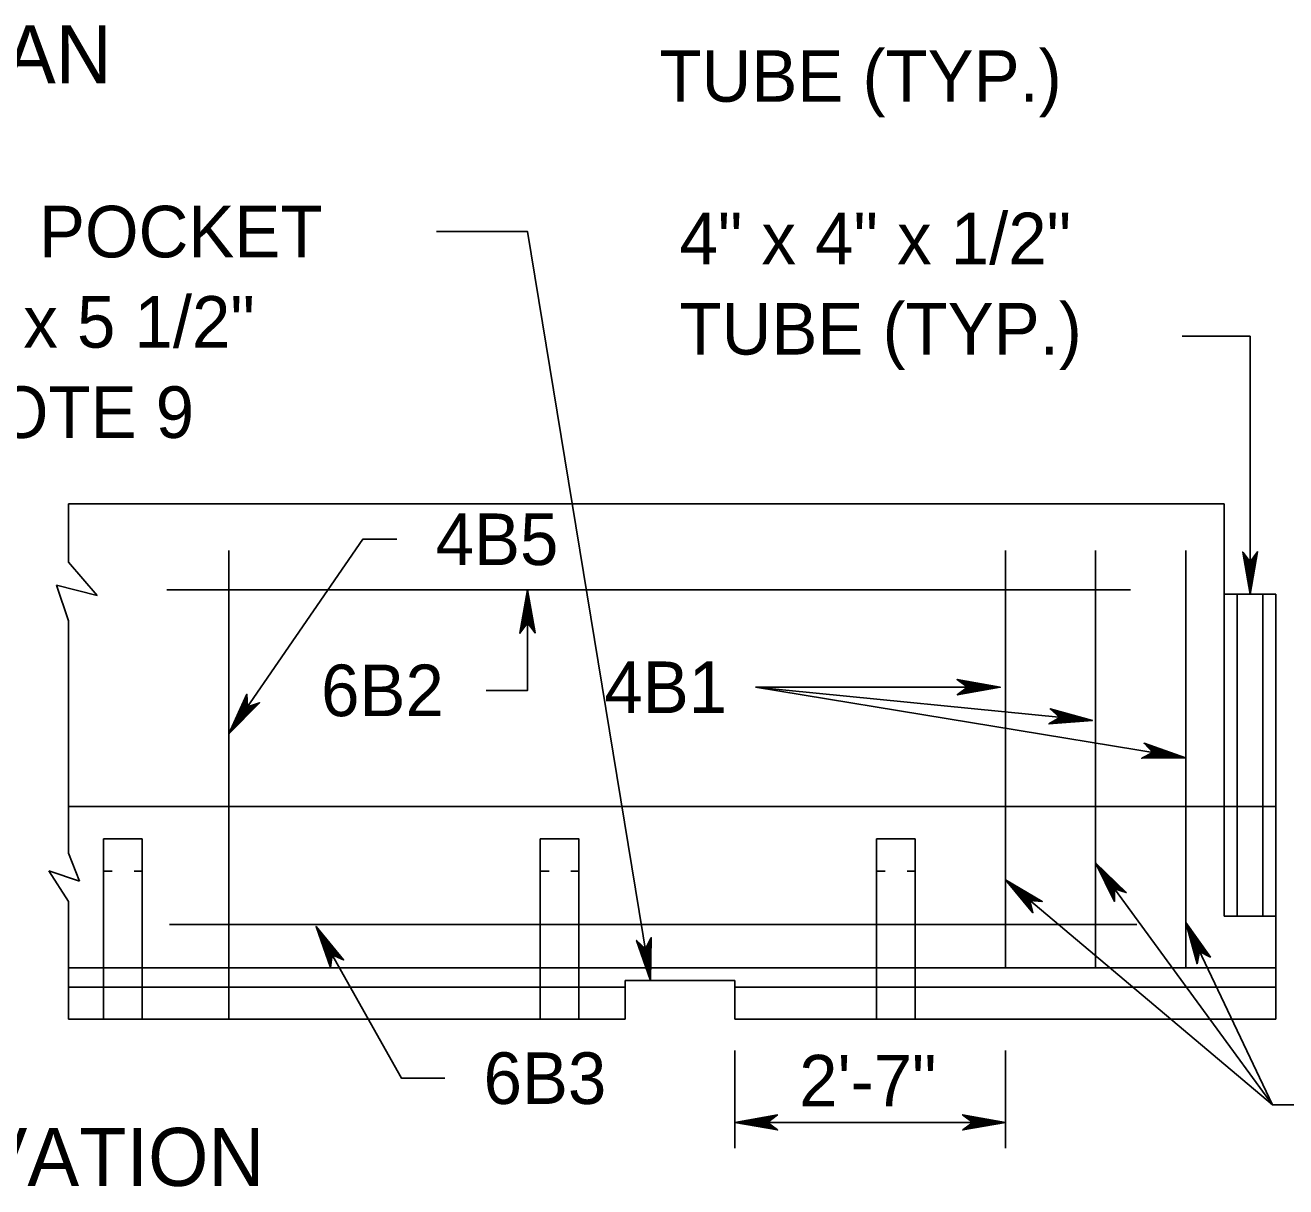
# Model space of a CAD drawing. Extents: x 499866 to 500993, y 499985 to 500645.
# Drawn here: x 500361.2 to 500459, y 500116.7 to 500206.8 of the extents above; entities that cross this region are included whole.
import ezdxf

# ---------------------------------------------------------------- set-up
doc = ezdxf.new("R2010")
doc.units = 0
doc.layers.add('24', color=7, linetype='Continuous')
doc.layers.add('5', color=7, linetype='Continuous')

msp = doc.modelspace()

# ---------------------------------------------------------------- linework, layer by layer
at = {"layer": '24'}
for points in [[(500456.223, 500162.67), (500456.802, 500165.944), (500456.223, 500165.162), (500455.653, 500165.927), (500456.223, 500162.67), (500456.217, 500162.887), (500456.759, 500165.852), (500456.216, 500165.101), (500455.698, 500165.795), (500456.207, 500163.005), (500456.223, 500163.114), (500456.675, 500165.654), (500456.216, 500165.084), (500455.772, 500165.67), (500456.223, 500163.164), (500456.207, 500163.273), (500456.608, 500165.493), (500456.223, 500165.061), (500455.824, 500165.502), (500456.206, 500163.589), (500456.207, 500163.773), (500456.525, 500165.328), (500456.232, 500165.026), (500455.907, 500165.351), (500456.223, 500163.806), (500456.233, 500163.981), (500456.433, 500165.15), (500456.206, 500164.925), (500455.982, 500165.169), (500456.223, 500164.142), (500456.24, 500164.307), (500456.374, 500165.009), (500456.216, 500164.893), (500456.041, 500165.084), (500456.223, 500164.392), (500456.332, 500164.85), (500456.207, 500164.784), (500456.081, 500164.985), (500456.206, 500164.508), (500456.282, 500164.808), (500456.183, 500164.682), (500456.124, 500164.826), (500456.216, 500164.683), (500456.232, 500164.758)], [(500400.181, 500162.984), (500400.181, 500155.199), (500396.976, 500155.199)], [(500400.181, 500162.984), (500399.589, 500159.634), (500400.181, 500160.434), (500400.764, 500159.651), (500400.181, 500162.984), (500400.187, 500162.761), (500399.633, 500159.727), (500400.189, 500160.496), (500400.719, 500159.786), (500400.198, 500162.641), (500400.181, 500162.53), (500399.72, 500159.931), (500400.188, 500160.514), (500400.643, 500159.914), (500400.181, 500162.478), (500400.198, 500162.367), (500399.788, 500160.095), (500400.181, 500160.537), (500400.59, 500160.086), (500400.199, 500162.044), (500400.198, 500161.855), (500399.872, 500160.264), (500400.172, 500160.573), (500400.505, 500160.24), (500400.181, 500161.821), (500400.171, 500161.642), (500399.966, 500160.446), (500400.199, 500160.676), (500400.428, 500160.427), (500400.181, 500161.478), (500400.164, 500161.309), (500400.027, 500160.591), (500400.189, 500160.709), (500400.367, 500160.513), (500400.181, 500161.221), (500400.07, 500160.753), (500400.198, 500160.821), (500400.326, 500160.615), (500400.199, 500161.104), (500400.121, 500160.796), (500400.222, 500160.925), (500400.283, 500160.777), (500400.189, 500160.924), (500400.172, 500160.847)], [(500436.846, 500155.439), (500433.496, 500156.031), (500434.297, 500155.439), (500433.513, 500154.856), (500436.846, 500155.439), (500436.624, 500155.433), (500433.59, 500155.987), (500434.359, 500155.432), (500433.649, 500154.902), (500436.504, 500155.423), (500436.392, 500155.439), (500433.793, 500155.901), (500434.376, 500155.432), (500433.777, 500154.977), (500436.341, 500155.439), (500436.23, 500155.423), (500433.958, 500155.833), (500434.4, 500155.439), (500433.949, 500155.031), (500435.906, 500155.422), (500435.717, 500155.423), (500434.127, 500155.748), (500434.436, 500155.448), (500434.103, 500155.115), (500435.683, 500155.439), (500435.505, 500155.449), (500434.309, 500155.654), (500434.539, 500155.422), (500434.289, 500155.193), (500435.34, 500155.439), (500435.172, 500155.456), (500434.453, 500155.593), (500434.572, 500155.432), (500434.376, 500155.253), (500435.084, 500155.439), (500434.615, 500155.551), (500434.683, 500155.423), (500434.478, 500155.294), (500434.966, 500155.422), (500434.659, 500155.499), (500434.788, 500155.398), (500434.64, 500155.338), (500434.787, 500155.432), (500434.71, 500155.448)], [(500377.004, 500151.821), (500379.393, 500154.243), (500378.451, 500153.92), (500378.415, 500154.896), (500377.004, 500151.821), (500377.126, 500152.008), (500379.303, 500154.191), (500378.409, 500153.873), (500378.376, 500154.759), (500377.185, 500152.112), (500377.262, 500152.195), (500379.117, 500154.073), (500378.4, 500153.859), (500378.366, 500154.61), (500377.291, 500152.237), (500377.341, 500152.338), (500378.967, 500153.976), (500378.392, 500153.835), (500378.312, 500154.438), (500377.524, 500152.605), (500377.631, 500152.76), (500378.802, 500153.885), (500378.38, 500153.8), (500378.295, 500154.263), (500377.664, 500152.778), (500377.774, 500152.92), (500378.621, 500153.788), (500378.3, 500153.731), (500378.252, 500154.066), (500377.859, 500153.061), (500377.969, 500153.19), (500378.489, 500153.704), (500378.289, 500153.698), (500378.253, 500153.96), (500378.004, 500153.272), (500378.362, 500153.594), (500378.218, 500153.611), (500378.229, 500153.853), (500378.057, 500153.379), (500378.295, 500153.588), (500378.138, 500153.539), (500378.173, 500153.695), (500378.167, 500153.521), (500378.224, 500153.574)], [(500444.002, 500152.857), (500440.726, 500153.776), (500441.465, 500153.108), (500440.628, 500152.604), (500444.002, 500152.857), (500443.78, 500152.873), (500440.815, 500153.722), (500441.526, 500153.094), (500440.767, 500152.637), (500443.659, 500152.874), (500443.55, 500152.902), (500441.009, 500153.617), (500441.543, 500153.093), (500440.902, 500152.699), (500443.499, 500152.907), (500443.387, 500152.901), (500441.167, 500153.532), (500441.568, 500153.098), (500441.078, 500152.735), (500443.065, 500152.932), (500442.877, 500152.951), (500441.326, 500153.432), (500441.604, 500153.103), (500441.24, 500152.804), (500442.845, 500152.971), (500442.668, 500152.999), (500441.498, 500153.321), (500441.704, 500153.067), (500441.433, 500152.863), (500442.503, 500153.005), (500442.337, 500153.038), (500441.636, 500153.245), (500441.738, 500153.073), (500441.526, 500152.915), (500442.248, 500153.031), (500441.793, 500153.187), (500441.848, 500153.053), (500441.631, 500152.946), (500442.13, 500153.025), (500441.831, 500153.132), (500441.949, 500153.018), (500441.796, 500152.973), (500441.952, 500153.052), (500441.877, 500153.076)], [(500451.208, 500149.974), (500447.998, 500151.1), (500448.692, 500150.386), (500447.825, 500149.938), (500451.208, 500149.974), (500450.988, 500150.004), (500448.084, 500151.042), (500448.753, 500150.369), (500447.966, 500149.961), (500450.868, 500150.013), (500450.76, 500150.048), (500448.27, 500150.924), (500448.77, 500150.366), (500448.105, 500150.015), (500450.71, 500150.056), (500450.597, 500150.057), (500448.422, 500150.829), (500448.794, 500150.37), (500448.283, 500150.039), (500450.278, 500150.109), (500450.092, 500150.14), (500448.574, 500150.719), (500448.831, 500150.373), (500448.449, 500150.098), (500450.061, 500150.162), (500449.886, 500150.201), (500448.739, 500150.597), (500448.928, 500150.33), (500448.645, 500150.145), (500449.722, 500150.218), (500449.559, 500150.262), (500448.872, 500150.513), (500448.963, 500150.335), (500448.74, 500150.19), (500449.47, 500150.259), (500449.025, 500150.445), (500449.072, 500150.307), (500448.848, 500150.214), (500449.35, 500150.261), (500449.059, 500150.387), (500449.17, 500150.266), (500449.015, 500150.231), (500449.175, 500150.3), (500449.102, 500150.329)], [(500444.239, 500141.817), (500445.706, 500138.834), (500445.711, 500139.806), (500446.622, 500139.525), (500444.239, 500141.817), (500444.372, 500141.645), (500445.687, 500138.933), (500445.681, 500139.86), (500446.508, 500139.606), (500444.45, 500141.556), (500444.501, 500141.459), (500445.637, 500139.143), (500445.67, 500139.873), (500446.375, 500139.663), (500444.531, 500141.419), (500444.608, 500141.341), (500445.596, 500139.312), (500445.651, 500139.888), (500446.234, 500139.768), (500444.795, 500141.086), (500444.904, 500140.936), (500445.565, 500139.494), (500445.623, 500139.911), (500446.078, 500139.84), (500444.91, 500140.9), (500445.005, 500140.753), (500445.534, 500139.692), (500445.584, 500140.007), (500445.909, 500139.943), (500445.108, 500140.63), (500445.193, 500140.487), (500445.499, 500139.841), (500445.558, 500140.028), (500445.812, 500139.976), (500445.256, 500140.427), (500445.439, 500139.994), (500445.501, 500140.121), (500445.72, 500140.033), (500445.338, 500140.344), (500445.454, 500140.058), (500445.46, 500140.218), (500445.593, 500140.136), (500445.433, 500140.198), (500445.465, 500140.127)], [(500437.244, 500140.501), (500439.376, 500137.95), (500439.151, 500138.896), (500440.103, 500138.839), (500437.244, 500140.501), (500437.414, 500140.365), (500439.334, 500138.041), (500439.108, 500138.941), (500439.973, 500138.89), (500437.511, 500140.297), (500437.584, 500140.215), (500439.236, 500138.234), (500439.095, 500138.951), (500439.83, 500138.914), (500437.622, 500140.182), (500437.716, 500140.125), (500439.156, 500138.389), (500439.073, 500138.961), (500439.668, 500138.983), (500437.958, 500139.922), (500438.098, 500139.802), (500439.083, 500138.558), (500439.04, 500138.976), (500439.499, 500139.016), (500438.114, 500139.769), (500438.24, 500139.649), (500439.006, 500138.743), (500438.98, 500139.061), (500439.311, 500139.076), (500438.37, 500139.553), (500438.486, 500139.434), (500438.936, 500138.879), (500438.949, 500139.074), (500439.208, 500139.085), (500438.561, 500139.391), (500438.842, 500139.013), (500438.872, 500139.152), (500439.106, 500139.119), (500438.661, 500139.33), (500438.842, 500139.079), (500438.809, 500139.236), (500438.958, 500139.188), (500438.789, 500139.21), (500438.836, 500139.149)], [(500383.782, 500136.901), (500390.403, 500125.131), (500393.772, 500125.131)], [(500383.782, 500136.901), (500384.9, 500133.716), (500385.023, 500134.697), (500385.907, 500134.303), (500383.782, 500136.901), (500383.896, 500136.712), (500384.892, 500133.819), (500384.998, 500134.754), (500385.802, 500134.398), (500383.963, 500136.613), (500384.003, 500136.509), (500384.868, 500134.037), (500384.99, 500134.769), (500385.675, 500134.472), (500384.028, 500136.464), (500384.096, 500136.377), (500384.847, 500134.212), (500384.972, 500134.786), (500385.545, 500134.594), (500384.254, 500136.096), (500384.346, 500135.933), (500384.838, 500134.399), (500384.947, 500134.812), (500385.397, 500134.686), (500384.348, 500135.896), (500384.426, 500135.736), (500384.831, 500134.602), (500384.919, 500134.914), (500385.239, 500134.81), (500384.515, 500135.599), (500384.582, 500135.445), (500384.813, 500134.757), (500384.895, 500134.938), (500385.145, 500134.856), (500384.639, 500135.377), (500384.771, 500134.918), (500384.849, 500135.039), (500385.06, 500134.924), (500384.712, 500135.284), (500384.794, 500134.98), (500384.819, 500135.141), (500384.943, 500135.043), (500384.79, 500135.124), (500384.813, 500135.049)], [(500451.234, 500137.21), (500452.118, 500134.006), (500452.305, 500134.961), (500453.149, 500134.515), (500451.234, 500137.21), (500451.332, 500137.017), (500452.118, 500134.107), (500452.285, 500135.019), (500453.051, 500134.615), (500451.392, 500136.915), (500451.425, 500136.81), (500452.109, 500134.323), (500452.277, 500135.034), (500452.931, 500134.696), (500451.445, 500136.764), (500451.507, 500136.673), (500452.1, 500134.497), (500452.261, 500135.052), (500452.811, 500134.826), (500451.643, 500136.388), (500451.722, 500136.221), (500452.104, 500134.681), (500452.238, 500135.08), (500452.672, 500134.926), (500451.722, 500136.184), (500451.788, 500136.022), (500452.11, 500134.881), (500452.218, 500135.182), (500452.525, 500135.058), (500451.866, 500135.882), (500451.922, 500135.726), (500452.103, 500135.034), (500452.196, 500135.206), (500452.436, 500135.109), (500451.974, 500135.656), (500452.073, 500135.196), (500452.157, 500135.309), (500452.357, 500135.182), (500452.039, 500135.558), (500452.1, 500135.255), (500452.135, 500135.411), (500452.25, 500135.306), (500452.105, 500135.396), (500452.122, 500135.322)], [(500409.731, 500132.693), (500409.771, 500136.017), (500409.327, 500135.152), (500408.641, 500135.815), (500409.731, 500132.693), (500409.69, 500132.906), (500409.743, 500135.92), (500409.33, 500135.09), (500408.706, 500135.692), (500409.661, 500133.021), (500409.659, 500133.131), (500409.693, 500135.71), (500409.333, 500135.074), (500408.799, 500135.58), (500409.651, 500133.18), (500409.617, 500133.285), (500409.653, 500135.541), (500409.344, 500135.052), (500408.878, 500135.422), (500409.565, 500133.596), (500409.536, 500133.779), (500409.598, 500135.365), (500409.358, 500135.019), (500408.984, 500135.287), (500409.547, 500133.814), (500409.529, 500133.988), (500409.536, 500135.174), (500409.349, 500134.915), (500409.088, 500135.12), (500409.492, 500134.145), (500409.482, 500134.311), (500409.5, 500135.025), (500409.364, 500134.885), (500409.16, 500135.046), (500409.452, 500134.392), (500409.485, 500134.862), (500409.372, 500134.776), (500409.216, 500134.954), (500409.417, 500134.503), (500409.442, 500134.812), (500409.365, 500134.672), (500409.283, 500134.805), (500409.397, 500134.678), (500409.402, 500134.755)], [(500416.254, 500121.701), (500419.577, 500121.114), (500418.783, 500121.701), (500419.56, 500122.28), (500416.254, 500121.701), (500416.474, 500121.708), (500419.484, 500121.157), (500418.721, 500121.708), (500419.426, 500122.234), (500416.594, 500121.718), (500416.704, 500121.701), (500419.283, 500121.243), (500418.704, 500121.708), (500419.299, 500122.159), (500416.755, 500121.701), (500416.865, 500121.718), (500419.119, 500121.311), (500418.681, 500121.701), (500419.128, 500122.107), (500417.186, 500121.718), (500417.374, 500121.718), (500418.952, 500121.395), (500418.645, 500121.692), (500418.975, 500122.023), (500417.407, 500121.701), (500417.585, 500121.691), (500418.771, 500121.488), (500418.543, 500121.718), (500418.79, 500121.946), (500417.748, 500121.701), (500417.915, 500121.684), (500418.628, 500121.548), (500418.51, 500121.708), (500418.705, 500121.886), (500418.002, 500121.701), (500418.467, 500121.591), (500418.4, 500121.718), (500418.604, 500121.845), (500418.119, 500121.718), (500418.424, 500121.642), (500418.296, 500121.742), (500418.443, 500121.802), (500418.297, 500121.708), (500418.373, 500121.692)], [(500437.244, 500121.701), (500433.921, 500122.289), (500434.714, 500121.701), (500433.937, 500121.123), (500437.244, 500121.701), (500437.023, 500121.695), (500434.013, 500122.245), (500434.777, 500121.694), (500434.072, 500121.169), (500436.905, 500121.685), (500436.794, 500121.701), (500434.215, 500122.159), (500434.794, 500121.695), (500434.199, 500121.243), (500436.743, 500121.702), (500436.633, 500121.685), (500434.379, 500122.092), (500434.817, 500121.702), (500434.37, 500121.296), (500436.311, 500121.684), (500436.124, 500121.685), (500434.546, 500122.008), (500434.853, 500121.711), (500434.523, 500121.38), (500436.091, 500121.701), (500435.913, 500121.712), (500434.726, 500121.915), (500434.955, 500121.684), (500434.708, 500121.457), (500435.75, 500121.701), (500435.582, 500121.718), (500434.87, 500121.854), (500434.988, 500121.694), (500434.793, 500121.517), (500435.496, 500121.702), (500435.031, 500121.812), (500435.098, 500121.685), (500434.894, 500121.558), (500435.379, 500121.684), (500435.074, 500121.761), (500435.202, 500121.66), (500435.055, 500121.6), (500435.201, 500121.694), (500435.124, 500121.711)]]:
    msp.add_lwpolyline(points, dxfattribs=at)
at = {"layer": '5'}
for p, q in [((500454.224, 500169.665), (500364.572, 500169.665)), ((500364.572, 500169.665), (500364.572, 500165.134)), ((500454.224, 500169.665), (500454.224, 500162.67)), ((500377.004, 500166.05), (500377.004, 500129.696)), ((500437.244, 500166.05), (500437.244, 500133.692)), ((500444.239, 500166.05), (500444.239, 500133.692)), ((500451.234, 500166.05), (500451.234, 500133.692)), ((500364.572, 500165.134), (500366.809, 500162.562)), ((500364.572, 500160.583), (500363.643, 500163.353)), ((500363.643, 500163.353), (500366.809, 500162.562)), ((500372.202, 500162.984), (500446.941, 500162.984)), ((500454.224, 500162.67), (500454.224, 500137.689)), ((500458.222, 500162.67), (500454.224, 500162.67)), ((500455.224, 500162.67), (500455.224, 500137.689)), ((500457.222, 500162.67), (500457.222, 500137.689)), ((500458.222, 500162.67), (500458.222, 500129.696)), ((500364.572, 500160.583), (500364.572, 500142.579)), ((500417.853, 500155.439), (500436.846, 500155.439)), ((500417.853, 500155.439), (500444.002, 500152.857)), ((500417.853, 500155.439), (500451.208, 500149.974)), ((500458.222, 500146.183), (500364.572, 500146.183)), ((500367.291, 500143.685), (500367.291, 500129.696)), ((500370.288, 500143.685), (500370.288, 500129.696)), ((500401.165, 500143.685), (500401.165, 500129.696)), ((500404.163, 500143.685), (500404.163, 500129.696)), ((500427.245, 500143.685), (500427.245, 500129.696)), ((500430.243, 500143.685), (500430.243, 500129.696)), ((500364.572, 500142.579), (500365.424, 500140.403)), ((500444.239, 500141.817), (500457.976, 500123.053)), ((500364.572, 500138.82), (500363.05, 500141.194)), ((500363.05, 500141.194), (500365.424, 500140.403)), ((500364.572, 500138.82), (500364.572, 500129.696)), ((500458.222, 500137.689), (500454.224, 500137.689)), ((500372.409, 500137.051), (500447.429, 500137.051)), ((500451.234, 500137.21), (500457.976, 500123.053)), ((500395.397, 500133.692), (500364.572, 500133.692)), ((500371.334, 500133.692), (500366.09, 500133.692)), ((500458.222, 500133.692), (500395.397, 500133.692)), ((500416.254, 500132.693), (500407.76, 500132.693)), ((500407.76, 500132.693), (500407.76, 500129.696)), ((500416.254, 500132.693), (500416.254, 500129.696)), ((500407.76, 500132.194), (500364.572, 500132.194)), ((500458.222, 500132.194), (500416.254, 500132.194)), ((500395.397, 500129.696), (500364.572, 500129.696)), ((500371.334, 500129.696), (500366.09, 500129.696)), ((500407.76, 500129.696), (500395.397, 500129.696)), ((500458.222, 500129.696), (500416.254, 500129.696)), ((500416.254, 500127.281), (500416.254, 500119.703)), ((500437.244, 500127.281), (500437.244, 500119.703)), ((500416.254, 500121.701), (500437.244, 500121.701))]:
    msp.add_line(p, q, dxfattribs=at)
for points in [[(500393.131, 500190.771), (500400.188, 500190.771), (500409.731, 500132.693)], [(500450.949, 500182.655), (500456.223, 500182.655), (500456.223, 500162.67)], [(500390.054, 500166.915), (500387.405, 500166.915), (500377.004, 500151.821)], [(500369.673, 500141.172), (500370.283, 500141.172), (500370.288, 500143.685), (500367.291, 500143.685)], [(500367.291, 500143.685), (500367.291, 500141.172), (500367.972, 500141.172)], [(500403.547, 500141.172), (500404.157, 500141.172), (500404.163, 500143.685), (500401.165, 500143.685)], [(500401.165, 500143.685), (500401.165, 500141.172), (500401.846, 500141.172)], [(500429.628, 500141.172), (500430.238, 500141.172), (500430.243, 500143.685), (500427.245, 500143.685)], [(500427.245, 500143.685), (500427.245, 500141.172), (500427.927, 500141.172)], [(500437.244, 500140.501), (500457.976, 500123.053), (500462.653, 500123.053)]]:
    msp.add_lwpolyline(points, dxfattribs=at)

# ---------------------------------------------------------------- texts
for s, height, p in [('PLAN', 4.5, (500352.211, 500202.272)), ('TUBE (TYP.)', 4, (500410.412, 500200.837)), ('DRAINAGE POCKET', 4, (500332.857, 500188.771)), ('4" x 4" x 1/2"', 4, (500411.97, 500188.236)), ('2 5/8" x 5 1/2"', 4, (500345.793, 500181.771)), ('TUBE (TYP.)', 4, (500411.97, 500181.236)), ('SEE NOTE 9', 4, (500342.808, 500174.771)), ('4B5', 4, (500393.054, 500164.915)), ('6B2', 4, (500384.169, 500153.199)), ('4B1', 4, (500406.145, 500153.439)), ('6B3', 4, (500396.772, 500123.131)), ('2\'-7"', 4, (500421.249, 500122.935)), ('ELEVATION', 4.5, (500346.001, 500116.773))]:
    msp.add_text(s, height=height, dxfattribs=at).set_placement(p)

doc.saveas('drawing.dxf')
